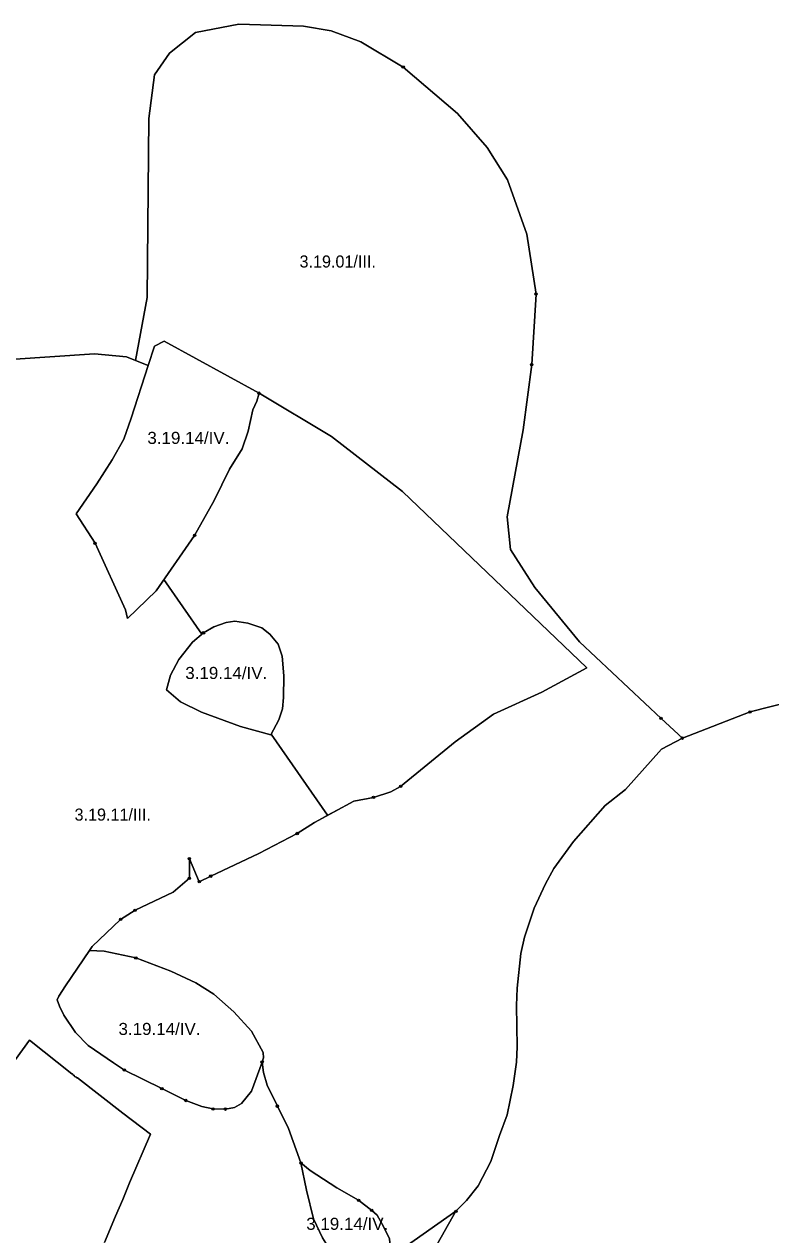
# Model space of a CAD drawing. Extents: x -650455 to -642254, y -1075222 to -1066610.
# Drawn here: x -645652 to -645034, y -1073114 to -1072112 of the extents above; entities that cross this region are included whole.
import ezdxf
from ezdxf.enums import TextEntityAlignment as Align

# ---------------------------------------------------------------- set-up
doc = ezdxf.new("R2010")
doc.units = 0
doc.header["$LTSCALE"] = 4
doc.header["$PDMODE"] = 32
doc.header["$PDSIZE"] = 2
for name, color, linetype, lineweight in [('1', 7, 'Continuous', 25), ('11', 7, 'Continuous', 13), ('13', 7, 'Continuous', 13), ('14', 7, 'Continuous', 13)]:
    doc.layers.add(name, color=color, linetype=linetype, lineweight=lineweight)
doc.layers.add('2', color=7, linetype='Continuous')

msp = doc.modelspace()

# ---------------------------------------------------------------- linework, layer by layer
at = {"layer": '1'}
for points in [[(-645000, -1072668.218), (-645051.292, -1072681.171), (-645107.317, -1072702.887), (-645125, -1072686.501), (-645192.5, -1072623), (-645229.5, -1072578), (-645249.5, -1072546.5), (-645252.5, -1072519.501), (-645239, -1072447.501), (-645232, -1072393.5), (-645228.5, -1072335.001), (-645236, -1072285.501), (-645252, -1072240.501), (-645269, -1072213.501), (-645293.5, -1072185.5), (-645338.5, -1072147.001), (-645373.5, -1072126), (-645398, -1072117), (-645421, -1072113), (-645474.5, -1072111.501), (-645510.5, -1072118.5), (-645532, -1072135.501), (-645544.5, -1072153.5), (-645549, -1072189.5), (-645550.5, -1072338.001), (-645560, -1072390.001), (-645567.5, -1072387.001), (-645594, -1072384.5), (-645697, -1072391.501)], [(-645464.113, -1072945.509), (-645478.626, -1072929.598), (-645495.238, -1072915.084), (-645510.188, -1072905.467), (-645530.996, -1072896.025), (-645559.847, -1072885.009), (-645586.076, -1072879.478), (-645598.235, -1072878.802), (-645596, -1072875.5), (-645572.5, -1072853.001), (-645560.5, -1072845.5), (-645529, -1072830.5), (-645515.5, -1072819.001), (-645515.5, -1072802.829), (-645507.327, -1072821.847), (-645497.861, -1072817.229), (-645457.907, -1072798.52), (-645426.258, -1072781.908), (-645411.919, -1072772.641), (-645379.484, -1072754.98), (-645363.047, -1072752.008), (-645348.709, -1072747.462), (-645340.665, -1072742.916), (-645295.465, -1072705.846), (-645263.816, -1072683.115), (-645223.774, -1072664.929), (-645186.442, -1072644.646), (-645339.092, -1072498.466), (-645397.843, -1072453.003), (-645457.819, -1072417.158), (-645536.33, -1072373.968), (-645544.373, -1072378.165), (-645549.565, -1072394.297), (-645560, -1072390.001), (-645550.5, -1072338.001), (-645549, -1072189.5), (-645544.5, -1072153.5), (-645532, -1072135.501), (-645510.5, -1072118.5), (-645474.5, -1072111.501)], [(-645474.5, -1072111.501), (-645421, -1072113), (-645398, -1072117), (-645373.5, -1072126), (-645338.5, -1072147.001), (-645293.5, -1072185.5), (-645269, -1072213.501), (-645252, -1072240.501), (-645236, -1072285.501), (-645228.5, -1072335.001), (-645232, -1072393.5), (-645239, -1072447.501), (-645252.5, -1072519.501), (-645249.5, -1072546.5), (-645229.5, -1072578), (-645192.5, -1072623), (-645125, -1072686.501), (-645107.317, -1072702.887)], [(-645697, -1072391.501), (-645594, -1072384.5), (-645567.5, -1072387.001), (-645560, -1072390.001)], [(-645560, -1072390.001), (-645549.565, -1072394.297), (-645563.782, -1072437.791), (-645569.902, -1072455.277), (-645579.344, -1072472.413), (-645592.021, -1072492.346), (-645609.332, -1072517.001), (-645593.595, -1072541.481), (-645568.328, -1072596.561), (-645566.755, -1072603.73), (-645543.149, -1072580.998), (-645511.15, -1072535.011), (-645495.063, -1072506.16), (-645482.212, -1072480.106), (-645471.72, -1072463.145), (-645466.824, -1072448.632), (-645463.065, -1072430.972), (-645459.568, -1072423.628), (-645457.819, -1072417.158), (-645397.843, -1072453.003), (-645339.092, -1072498.466), (-645186.442, -1072644.646), (-645223.774, -1072664.929), (-645263.816, -1072683.115), (-645295.465, -1072705.846), (-645340.665, -1072742.916), (-645348.709, -1072747.462), (-645363.047, -1072752.008), (-645379.484, -1072754.98), (-645411.919, -1072772.641), (-645426.258, -1072781.908), (-645457.907, -1072798.52), (-645497.861, -1072817.229), (-645507.327, -1072821.847), (-645515.5, -1072802.829), (-645515.5, -1072819.001), (-645529, -1072830.5), (-645560.5, -1072845.5), (-645572.5, -1072853.001), (-645596, -1072875.5)], [(-645247.379, -1072990.622), (-645244.668, -1072971.213), (-645244.144, -1072958.624), (-645244.581, -1072924.352), (-645244.056, -1072910.014), (-645241.171, -1072881.337), (-645238.024, -1072867.873), (-645229.98, -1072843.743), (-645220.713, -1072823.634), (-645213.806, -1072810.87), (-645197.37, -1072788.488), (-645171.229, -1072758.763), (-645154.442, -1072745.474), (-645124.542, -1072712.076), (-645107.317, -1072702.887), (-645051.292, -1072681.171), (-645000, -1072668.218)], [(-645107.317, -1072702.887), (-645124.542, -1072712.076), (-645154.442, -1072745.474), (-645171.229, -1072758.763), (-645197.37, -1072788.488), (-645213.806, -1072810.87), (-645220.713, -1072823.634), (-645229.98, -1072843.743), (-645238.024, -1072867.873), (-645241.171, -1072881.337), (-645244.056, -1072910.014), (-645244.581, -1072924.352), (-645244.144, -1072958.624), (-645244.668, -1072971.213), (-645247.379, -1072990.622), (-645252.275, -1073014.927), (-645258.744, -1073032.063), (-645265.913, -1073053.571), (-645276.492, -1073073.679), (-645286.109, -1073085.919), (-645294.852, -1073094.837), (-645336.905, -1073124.213)], [(-645596, -1072875.5), (-645598.235, -1072878.802), (-645618, -1072908), (-645623.5, -1072916.501), (-645625.037, -1072919.546), (-645623.058, -1072924.876), (-645619.385, -1072932.395), (-645609.768, -1072946.733), (-645599.277, -1072957.574), (-645578.469, -1072971.913), (-645569.377, -1072977.858), (-645538.34, -1072993.245), (-645518.581, -1073003.037), (-645505.117, -1073007.933), (-645496.024, -1073010.031), (-645485.708, -1073010.206), (-645478.189, -1073008.807), (-645472.244, -1073005.485), (-645464.201, -1072995.343), (-645455.283, -1072971.213), (-645454.234, -1072979.956), (-645451.086, -1072990.447), (-645442.606, -1073007.758), (-645433.338, -1073026.118), (-645423.109, -1073054.795), (-645418.563, -1073077.351), (-645412.618, -1073101.131), (-645405.274, -1073116.694)], [(-645609.115, -1072983.715), (-645610.526, -1072983.151), (-645610.949, -1072982.163), (-645611.655, -1072982.022), (-645612.36, -1072980.893), (-645612.924, -1072980.893), (-645648.03, -1072953.171), (-645659.633, -1072969.042)], [(-645349.844, -1073117.568), (-645354.74, -1073107.426), (-645360.161, -1073098.159), (-645364.532, -1073094.137), (-645375.373, -1073085.744), (-645393.558, -1073075.428), (-645415.59, -1073061.089), (-645423.109, -1073054.795), (-645433.338, -1073026.118), (-645442.606, -1073007.758), (-645451.086, -1072990.447), (-645454.234, -1072979.956), (-645455.283, -1072971.213), (-645454.146, -1072967.716), (-645454.496, -1072963.17), (-645464.113, -1072945.509)], [(-645585.831, -1073120.596), (-645576.8, -1073098.864), (-645570.591, -1073085.034), (-645565.087, -1073071.205), (-645547.791, -1073030.888), (-645570.732, -1073013.631), (-645608.127, -1072984.42), (-645608.974, -1072984.279), (-645609.115, -1072983.715)], [(-645316.797, -1073133.48), (-645301.06, -1073105.503), (-645294.852, -1073094.837), (-645286.109, -1073085.919), (-645276.492, -1073073.679), (-645265.913, -1073053.571), (-645258.744, -1073032.063), (-645252.275, -1073014.927), (-645247.379, -1072990.622)], [(-645336.905, -1073124.213), (-645294.852, -1073094.837), (-645301.06, -1073105.503), (-645316.797, -1073133.48)]]:
    msp.add_lwpolyline(points, dxfattribs=at)
for points in [[(-645457.819, -1072417.158), (-645459.568, -1072423.628), (-645463.065, -1072430.972), (-645466.824, -1072448.632), (-645471.72, -1072463.145), (-645482.212, -1072480.106), (-645495.063, -1072506.16), (-645511.15, -1072535.011), (-645543.149, -1072580.998), (-645566.755, -1072603.73), (-645568.328, -1072596.561), (-645593.595, -1072541.481), (-645609.332, -1072517.001), (-645592.021, -1072492.346), (-645579.344, -1072472.413), (-645569.902, -1072455.277), (-645563.782, -1072437.791), (-645549.565, -1072394.297), (-645544.373, -1072378.165), (-645536.33, -1072373.968)], [(-645441.437, -1072687.696), (-645438.464, -1072678.603), (-645437.59, -1072669.336), (-645437.24, -1072651.151), (-645438.639, -1072634.889), (-645441.961, -1072624.922), (-645448.781, -1072616.704), (-645455.6, -1072611.458), (-645467.141, -1072607.611), (-645477.807, -1072606.038), (-645485.151, -1072607.087), (-645495.293, -1072610.759), (-645503.86, -1072615.655), (-645512.953, -1072623.523), (-645524.319, -1072637.687), (-645531.138, -1072650.626), (-645534.46, -1072662.866), (-645522.745, -1072672.833), (-645505.609, -1072681.401), (-645473.26, -1072693.291), (-645448.081, -1072700.285)], [(-645441.437, -1072687.696), (-645448.081, -1072700.285), (-645473.26, -1072693.291), (-645505.609, -1072681.401), (-645522.745, -1072672.833), (-645534.46, -1072662.866), (-645531.138, -1072650.626), (-645524.319, -1072637.687), (-645512.953, -1072623.523), (-645503.86, -1072615.655), (-645495.293, -1072610.759), (-645485.151, -1072607.087), (-645477.807, -1072606.038), (-645467.141, -1072607.611), (-645455.6, -1072611.458), (-645448.781, -1072616.704), (-645441.961, -1072624.922), (-645438.639, -1072634.889), (-645437.24, -1072651.151), (-645437.59, -1072669.336), (-645438.464, -1072678.603)], [(-645455.283, -1072971.213), (-645464.201, -1072995.343), (-645472.244, -1073005.485), (-645478.189, -1073008.807), (-645485.708, -1073010.206), (-645496.024, -1073010.031), (-645505.117, -1073007.933), (-645518.581, -1073003.037), (-645538.34, -1072993.245), (-645569.377, -1072977.858), (-645578.469, -1072971.913), (-645599.277, -1072957.574), (-645609.768, -1072946.733), (-645619.385, -1072932.395), (-645623.058, -1072924.876), (-645625.037, -1072919.546), (-645623.5, -1072916.501), (-645618, -1072908), (-645598.235, -1072878.802), (-645586.076, -1072879.478), (-645559.847, -1072885.009), (-645530.996, -1072896.025), (-645510.188, -1072905.467), (-645495.238, -1072915.084), (-645478.626, -1072929.598), (-645464.113, -1072945.509), (-645454.496, -1072963.17), (-645454.146, -1072967.716)], [(-645351.243, -1073131.207), (-645357.013, -1073138.376), (-645364.358, -1073140.474), (-645374.499, -1073140.125), (-645384.641, -1073137.152), (-645393.034, -1073132.256), (-645399.679, -1073125.611), (-645405.274, -1073116.694), (-645412.618, -1073101.131), (-645418.563, -1073077.351), (-645423.109, -1073054.795), (-645415.59, -1073061.089), (-645393.558, -1073075.428), (-645375.373, -1073085.744), (-645364.532, -1073094.137), (-645360.161, -1073098.159), (-645354.74, -1073107.426), (-645349.844, -1073117.568), (-645349.32, -1073124.038)]]:
    msp.add_lwpolyline(points, close=True, dxfattribs=at)
at = {"layer": '11'}
for points in [[(-646027.5, -1072126), (-646011, -1072139.501), (-645967.5, -1072184.501), (-645932, -1072243), (-645908.5, -1072283), (-645884.5, -1072309.501), (-645854, -1072327), (-645788.5, -1072351.001), (-645718.5, -1072394.001), (-645697, -1072391.501), (-645594, -1072384.5), (-645567.5, -1072387.001), (-645560, -1072390.001), (-645550.5, -1072338.001), (-645549, -1072189.5), (-645544.5, -1072153.5), (-645532, -1072135.501), (-645510.5, -1072118.5), (-645474.5, -1072111.501), (-645421, -1072113), (-645398, -1072117), (-645373.5, -1072126), (-645338.5, -1072147.001)], [(-645338.5, -1072147.001), (-645293.5, -1072185.5), (-645269, -1072213.501), (-645252, -1072240.501), (-645236, -1072285.501), (-645228.5, -1072335.001), (-645232, -1072393.5)], [(-645232, -1072393.5), (-645239, -1072447.501), (-645252.5, -1072519.501), (-645249.5, -1072546.5), (-645229.5, -1072578), (-645192.5, -1072623), (-645125, -1072686.501), (-645107.317, -1072702.887), (-645051.292, -1072681.171), (-645000, -1072668.218)]]:
    msp.add_lwpolyline(points, dxfattribs=at)
for p in [(-645338.5, -1072147.001), (-645232, -1072393.5)]:
    msp.add_point(p, dxfattribs=at)
at = {"layer": '13'}
for p, q in [((-645505.166, -1072616.785), (-645503.86, -1072615.655)), ((-645107.317, -1072702.887), (-645125, -1072686.501)), ((-645515.5, -1072802.829), (-645515.5, -1072819.001)), ((-645507.327, -1072821.847), (-645497.861, -1072817.229))]:
    msp.add_line(p, q, dxfattribs=at)
for points in [[(-645228.5, -1072335.001), (-645236, -1072285.501), (-645252, -1072240.501), (-645269, -1072213.501), (-645293.5, -1072185.5), (-645338.5, -1072147.001), (-645373.5, -1072126), (-645398, -1072117), (-645421, -1072113), (-645474.5, -1072111.501), (-645510.5, -1072118.5), (-645532, -1072135.501), (-645544.5, -1072153.5), (-645549, -1072189.5), (-645550.5, -1072338.001), (-645560, -1072390.001), (-645549.565, -1072394.297), (-645544.373, -1072378.165), (-645536.33, -1072373.968), (-645457.819, -1072417.158)], [(-645125, -1072686.501), (-645192.5, -1072623), (-645229.5, -1072578), (-645249.5, -1072546.5), (-645252.5, -1072519.501), (-645239, -1072447.501), (-645232, -1072393.5), (-645228.5, -1072335.001)], [(-645426.258, -1072781.908), (-645411.919, -1072772.641), (-645401.154, -1072766.779), (-645447.728, -1072699.616), (-645448.081, -1072700.285), (-645473.26, -1072693.291), (-645505.609, -1072681.401), (-645522.745, -1072672.833), (-645534.46, -1072662.866), (-645531.138, -1072650.626), (-645524.319, -1072637.687), (-645512.953, -1072623.523), (-645505.166, -1072616.785), (-645536.554, -1072571.521), (-645543.149, -1072580.998), (-645566.755, -1072603.73), (-645568.328, -1072596.561), (-645593.595, -1072541.481), (-645609.332, -1072517.001), (-645592.021, -1072492.346), (-645579.344, -1072472.413), (-645569.902, -1072455.277), (-645563.782, -1072437.791), (-645549.565, -1072394.297), (-645560, -1072390.001), (-645567.5, -1072387.001), (-645594, -1072384.5), (-645697, -1072391.501)], [(-645363.047, -1072752.008), (-645348.709, -1072747.462), (-645340.665, -1072742.916), (-645295.465, -1072705.846), (-645263.816, -1072683.115), (-645223.774, -1072664.929), (-645186.442, -1072644.646), (-645339.092, -1072498.466), (-645397.843, -1072453.003), (-645457.819, -1072417.158), (-645459.568, -1072423.628), (-645463.065, -1072430.972), (-645466.824, -1072448.632), (-645471.72, -1072463.145), (-645482.212, -1072480.106), (-645495.063, -1072506.16), (-645511.15, -1072535.011), (-645536.554, -1072571.521), (-645505.166, -1072616.785)], [(-645457.819, -1072417.158), (-645397.843, -1072453.003), (-645339.092, -1072498.466), (-645186.442, -1072644.646), (-645223.774, -1072664.929), (-645263.816, -1072683.115), (-645295.465, -1072705.846), (-645340.665, -1072742.916)], [(-645503.86, -1072615.655), (-645495.293, -1072610.759), (-645485.151, -1072607.087), (-645477.807, -1072606.038), (-645467.141, -1072607.611), (-645455.6, -1072611.458), (-645448.781, -1072616.704), (-645441.961, -1072624.922), (-645438.639, -1072634.889), (-645437.24, -1072651.151), (-645437.59, -1072669.336), (-645438.464, -1072678.603), (-645441.437, -1072687.696), (-645447.728, -1072699.616), (-645401.154, -1072766.779), (-645379.484, -1072754.98), (-645363.047, -1072752.008)], [(-644952, -1072647.5), (-644963.5, -1072659), (-645000, -1072668.218), (-645051.292, -1072681.171)], [(-645051.292, -1072681.171), (-645107.317, -1072702.887), (-645124.542, -1072712.076), (-645154.442, -1072745.474), (-645171.229, -1072758.763), (-645197.37, -1072788.488), (-645213.806, -1072810.87), (-645220.713, -1072823.634), (-645229.98, -1072843.743), (-645238.024, -1072867.873), (-645241.171, -1072881.337), (-645244.056, -1072910.014), (-645244.581, -1072924.352), (-645244.144, -1072958.624), (-645244.668, -1072971.213), (-645247.379, -1072990.622), (-645252.275, -1073014.927), (-645258.744, -1073032.063), (-645265.913, -1073053.571), (-645276.492, -1073073.679), (-645286.109, -1073085.919), (-645294.852, -1073094.837), (-645301.06, -1073105.503), (-645316.797, -1073133.48)], [(-645294.852, -1073094.837), (-645286.109, -1073085.919), (-645276.492, -1073073.679), (-645265.913, -1073053.571), (-645258.744, -1073032.063), (-645252.275, -1073014.927), (-645247.379, -1072990.622), (-645244.668, -1072971.213), (-645244.144, -1072958.624), (-645244.581, -1072924.352), (-645244.056, -1072910.014), (-645241.171, -1072881.337), (-645238.024, -1072867.873), (-645229.98, -1072843.743), (-645220.713, -1072823.634), (-645213.806, -1072810.87), (-645197.37, -1072788.488), (-645171.229, -1072758.763), (-645154.442, -1072745.474), (-645124.542, -1072712.076), (-645107.317, -1072702.887)], [(-645340.665, -1072742.916), (-645348.709, -1072747.462), (-645363.047, -1072752.008), (-645379.484, -1072754.98), (-645411.919, -1072772.641), (-645426.258, -1072781.908), (-645457.907, -1072798.52), (-645497.861, -1072817.229), (-645507.327, -1072821.847), (-645515.5, -1072802.829)], [(-645497.861, -1072817.229), (-645457.907, -1072798.52), (-645426.258, -1072781.908)], [(-645560.5, -1072845.5), (-645529, -1072830.5), (-645515.5, -1072819.001), (-645515.5, -1072802.829), (-645507.327, -1072821.847)], [(-645515.5, -1072819.001), (-645529, -1072830.5), (-645560.5, -1072845.5), (-645572.5, -1072853.001)], [(-645569.377, -1072977.858), (-645578.469, -1072971.913), (-645599.277, -1072957.574), (-645609.768, -1072946.733), (-645619.385, -1072932.395), (-645623.058, -1072924.876), (-645625.037, -1072919.546), (-645623.5, -1072916.501), (-645618, -1072908), (-645598.235, -1072878.802), (-645596, -1072875.5), (-645572.5, -1072853.001), (-645560.5, -1072845.5)], [(-645572.5, -1072853.001), (-645596, -1072875.5), (-645598.235, -1072878.802), (-645586.076, -1072879.478), (-645559.847, -1072885.009)], [(-645559.847, -1072885.009), (-645530.996, -1072896.025), (-645510.188, -1072905.467), (-645495.238, -1072915.084), (-645478.626, -1072929.598), (-645464.113, -1072945.509), (-645454.496, -1072963.17), (-645454.146, -1072967.716), (-645455.283, -1072971.213), (-645454.234, -1072979.956), (-645451.086, -1072990.447), (-645442.606, -1073007.758), (-645433.338, -1073026.118), (-645423.109, -1073054.795)], [(-645659.633, -1072969.042), (-645648.03, -1072953.171), (-645612.924, -1072980.893), (-645612.36, -1072980.893), (-645611.655, -1072982.022), (-645610.949, -1072982.163), (-645610.526, -1072983.151), (-645609.115, -1072983.715), (-645608.974, -1072984.279), (-645608.127, -1072984.42), (-645570.732, -1073013.631), (-645547.791, -1073030.888), (-645565.087, -1073071.205), (-645570.591, -1073085.034), (-645576.8, -1073098.864), (-645585.831, -1073120.596)], [(-645442.606, -1073007.758), (-645451.086, -1072990.447), (-645454.234, -1072979.956), (-645455.283, -1072971.213), (-645464.201, -1072995.343), (-645472.244, -1073005.485), (-645478.189, -1073008.807), (-645485.708, -1073010.206), (-645496.024, -1073010.031), (-645505.117, -1073007.933), (-645518.581, -1073003.037)], [(-645518.581, -1073003.037), (-645538.34, -1072993.245), (-645569.377, -1072977.858)], [(-645342.151, -1073221.608), (-645335.943, -1073197.478), (-645332.097, -1073178.418), (-645322.654, -1073149.042), (-645316.797, -1073133.48), (-645301.06, -1073105.503), (-645294.852, -1073094.837), (-645336.905, -1073124.213), (-645351.243, -1073131.207), (-645357.013, -1073138.376), (-645364.358, -1073140.474), (-645374.499, -1073140.125), (-645384.641, -1073137.152), (-645393.034, -1073132.256), (-645399.679, -1073125.611), (-645405.274, -1073116.694), (-645412.618, -1073101.131), (-645418.563, -1073077.351), (-645423.109, -1073054.795), (-645433.338, -1073026.118), (-645442.606, -1073007.758)], [(-645423.109, -1073054.795), (-645415.59, -1073061.089), (-645393.558, -1073075.428), (-645375.373, -1073085.744)], [(-645375.373, -1073085.744), (-645364.532, -1073094.137), (-645360.161, -1073098.159), (-645354.74, -1073107.426), (-645349.844, -1073117.568), (-645349.32, -1073124.038), (-645351.243, -1073131.207), (-645336.905, -1073124.213), (-645294.852, -1073094.837)]]:
    msp.add_lwpolyline(points, dxfattribs=at)
for p in [(-645228.5, -1072335.001), (-645457.819, -1072417.158), (-645503.86, -1072615.655), (-645051.292, -1072681.171), (-645125, -1072686.501), (-645107.317, -1072702.887), (-645340.665, -1072742.916), (-645363.047, -1072752.008), (-645426.258, -1072781.908), (-645515.5, -1072802.829), (-645515.5, -1072819.001), (-645507.327, -1072821.847), (-645497.861, -1072817.229), (-645572.5, -1072853.001), (-645560.5, -1072845.5), (-645559.847, -1072885.009), (-645569.377, -1072977.858), (-645518.581, -1073003.037), (-645442.606, -1073007.758), (-645423.109, -1073054.795), (-645375.373, -1073085.744), (-645294.852, -1073094.837)]:
    msp.add_point(p, dxfattribs=at)
at = {"layer": '14'}
msp.add_line((-645496.024, -1073010.031), (-645485.708, -1073010.206), dxfattribs=at)
for points in [[(-645511.15, -1072535.011), (-645495.063, -1072506.16), (-645482.212, -1072480.106), (-645471.72, -1072463.145), (-645466.824, -1072448.632), (-645463.065, -1072430.972), (-645459.568, -1072423.628), (-645457.819, -1072417.158), (-645536.33, -1072373.968), (-645544.373, -1072378.165), (-645549.565, -1072394.297), (-645563.782, -1072437.791), (-645569.902, -1072455.277), (-645579.344, -1072472.413), (-645592.021, -1072492.346), (-645609.332, -1072517.001), (-645593.595, -1072541.481)], [(-645593.595, -1072541.481), (-645568.328, -1072596.561), (-645566.755, -1072603.73), (-645543.149, -1072580.998), (-645543.109, -1072580.941), (-645511.15, -1072535.011)], [(-645455.283, -1072971.213), (-645454.146, -1072967.716), (-645454.496, -1072963.17), (-645464.113, -1072945.509), (-645478.626, -1072929.598), (-645495.238, -1072915.084), (-645510.188, -1072905.467), (-645530.996, -1072896.025), (-645559.847, -1072885.009), (-645586.076, -1072879.478), (-645598.235, -1072878.802), (-645618, -1072908), (-645623.5, -1072916.501), (-645625.037, -1072919.546), (-645623.058, -1072924.876), (-645619.385, -1072932.395), (-645609.768, -1072946.733), (-645599.277, -1072957.574), (-645578.469, -1072971.913), (-645569.377, -1072977.858), (-645538.34, -1072993.245)], [(-645485.708, -1073010.206), (-645478.189, -1073008.807), (-645472.244, -1073005.485), (-645464.201, -1072995.343), (-645455.283, -1072971.213)], [(-645538.34, -1072993.245), (-645518.581, -1073003.037), (-645505.117, -1073007.933), (-645496.024, -1073010.031)], [(-645364.532, -1073094.137), (-645375.373, -1073085.744), (-645393.558, -1073075.428), (-645415.59, -1073061.089), (-645423.109, -1073054.795), (-645418.563, -1073077.351), (-645412.618, -1073101.131), (-645405.274, -1073116.694), (-645399.679, -1073125.611), (-645393.034, -1073132.256), (-645384.641, -1073137.152)], [(-645384.641, -1073137.152), (-645374.499, -1073140.125), (-645364.358, -1073140.474), (-645357.013, -1073138.376), (-645351.243, -1073131.207), (-645349.32, -1073124.038), (-645349.844, -1073117.568), (-645354.74, -1073107.426), (-645360.161, -1073098.159), (-645364.532, -1073094.137)]]:
    msp.add_lwpolyline(points, dxfattribs=at)
msp.add_lwpolyline([(-645505.609, -1072681.401), (-645473.26, -1072693.291), (-645448.081, -1072700.285), (-645441.437, -1072687.696), (-645438.464, -1072678.603), (-645437.59, -1072669.336), (-645437.24, -1072651.151), (-645438.639, -1072634.889), (-645441.961, -1072624.922), (-645448.781, -1072616.704), (-645455.6, -1072611.458), (-645467.141, -1072607.611), (-645477.807, -1072606.038), (-645485.151, -1072607.087), (-645495.293, -1072610.759), (-645503.86, -1072615.655), (-645512.953, -1072623.523), (-645524.319, -1072637.687), (-645531.138, -1072650.626), (-645534.46, -1072662.866), (-645522.745, -1072672.833)], close=True, dxfattribs=at)
for p in [(-645593.595, -1072541.481), (-645511.15, -1072535.011), (-645455.283, -1072971.213), (-645538.34, -1072993.245), (-645496.024, -1073010.031), (-645485.708, -1073010.206), (-645364.532, -1073094.137)]:
    msp.add_point(p, dxfattribs=at)

# ---------------------------------------------------------------- texts
at = {"layer": '2'}
for s, p in [('3.19.01/III.', (-645392.712, -1072313.048)), ('3.19.11/III.', (-645579.002, -1072771.24))]:
    msp.add_text(s, height=10, dxfattribs=at).set_placement(p, align=Align.CENTER)
at = {"layer": '2', "width": 1.05}
for p in [(-645516.343, -1072459.176), (-645484.953, -1072653.904), (-645540.26, -1072948.768), (-645384.802, -1073110.205)]:
    msp.add_text('3.19.14/IV.', height=10, dxfattribs=at).set_placement(p, align=Align.CENTER)

doc.saveas('drawing.dxf')
